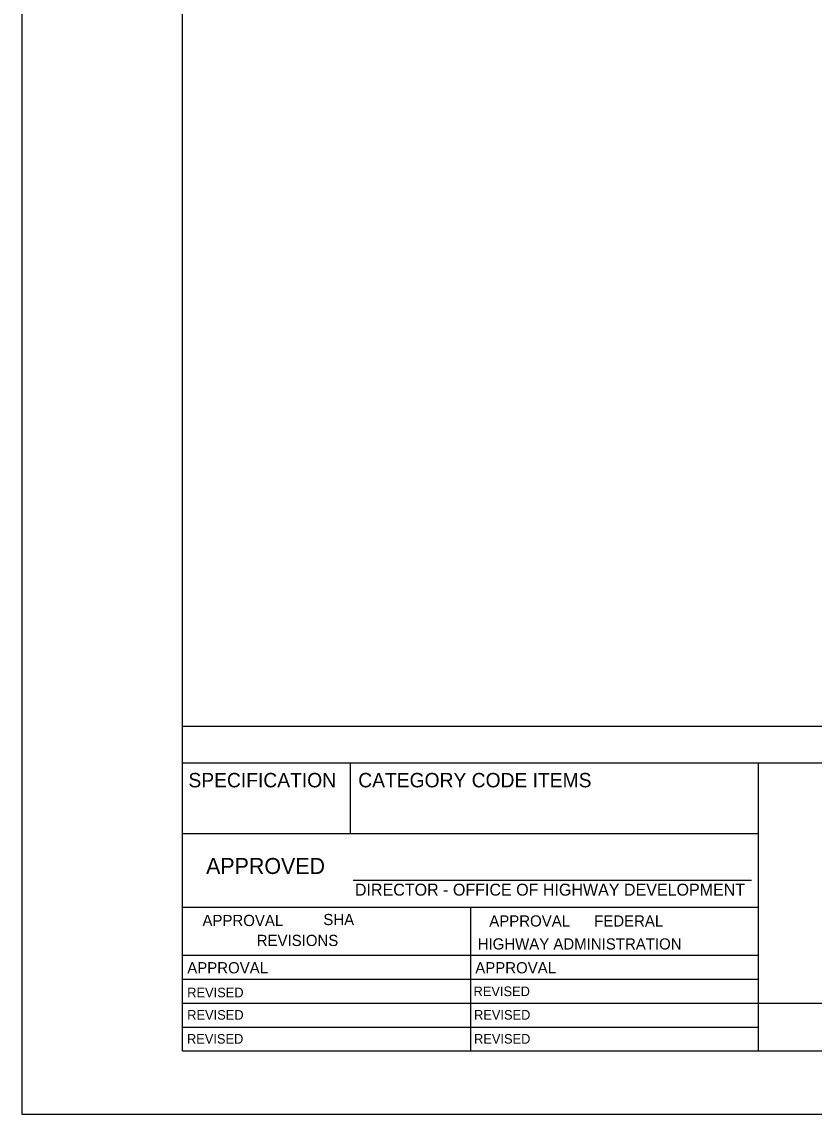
# Model space of a CAD drawing. Extents: x -0.5 to 19.9, y 5.2 to 17.3.
# Drawn here: x 11.44 to 15.43, y 5.67 to 11.17 of the extents above; entities that cross this region are included whole.
import ezdxf

# ---------------------------------------------------------------- set-up
doc = ezdxf.new("R2010")
doc.units = 0
for name, color, linetype in [('BORD-LINE', 7, 'Continuous'), ('TTLB-TEXT', 7, 'Continuous'), ('USER-CLIP', 7, 'Continuous')]:
    doc.layers.add(name, color=color, linetype=linetype)

msp = doc.modelspace()

# ---------------------------------------------------------------- linework, layer by layer
at = {"layer": 'BORD-LINE'}
for p, q in [((19.6208, 7.6193), (12.2466, 7.6193)), ((15.1479, 7.4352), (12.2466, 7.4352)), ((13.0928, 7.0805), (13.0928, 7.4352)), ((15.1479, 5.9844), (15.1479, 7.4352)), ((19.6208, 7.4352), (15.1479, 7.4352)), ((12.2466, 7.0805), (15.1479, 7.0805)), ((13.1058, 6.8454), (15.1127, 6.8454)), ((12.2466, 6.7098), (13.0928, 6.7098)), ((12.2466, 5.9844), (12.2466, 6.7098)), ((12.2466, 6.7098), (15.1479, 6.7098)), ((13.6972, 6.7098), (13.6972, 5.9844)), ((12.2466, 6.468), (15.1479, 6.468)), ((12.2466, 6.3471), (15.1479, 6.3471)), ((12.2466, 6.2262), (15.1479, 6.2262)), ((15.1479, 6.2262), (19.6208, 6.2262)), ((12.2466, 6.1053), (15.1479, 6.1053)), ((13.0928, 6.1053), (15.1479, 6.1053))]:
    msp.add_line(p, q, dxfattribs=at)
msp.add_lwpolyline([(12.2466, 16.3375), (19.6208, 16.3375), (19.6208, 5.9844), (12.2466, 5.9844)], close=True, dxfattribs=at)
at = {"layer": 'USER-CLIP'}
msp.add_lwpolyline([(19.9377, 16.6675), (11.4377, 16.6675), (11.4377, 5.6675), (19.9377, 5.6675)], close=True, dxfattribs=at)

# ---------------------------------------------------------------- texts
at = {"layer": 'TTLB-TEXT'}
for s, height, p in [('SPECIFICATION', 0.07254, (12.2768, 7.3131)), ('CATEGORY CODE ITEMS ', 0.07254, (13.1321, 7.3131)), ('APPROVED', 0.0806, (12.3658, 6.8768)), ('DIRECTOR - OFFICE OF HIGHWAY DEVELOPMENT', 0.0604, (13.1153, 6.7676)), ('APPROVAL', 0.05642, (12.3476, 6.6146)), ('SHA', 0.05642, (12.9562, 6.6193)), ('APPROVAL', 0.05642, (13.7921, 6.6121)), ('FEDERAL', 0.05642, (14.3202, 6.6122)), ('REVISIONS', 0.05642, (12.6207, 6.5141)), ('HIGHWAY ADMINISTRATION', 0.05642, (13.7336, 6.4964)), ('APPROVAL', 0.05642, (12.271, 6.3764)), ('APPROVAL', 0.05642, (13.7216, 6.3764)), ('REVISED', 0.04836, (12.2707, 6.2559)), ('REVISED', 0.04836, (13.7129, 6.2618)), ('REVISED', 0.04836, (12.2707, 6.1433)), ('REVISED', 0.04836, (13.7152, 6.1433)), ('REVISED', 0.04836, (12.2694, 6.0225)), ('REVISED', 0.04836, (13.7152, 6.0225))]:
    msp.add_text(s, height=height, dxfattribs=at).set_placement(p)

doc.saveas('drawing.dxf')
